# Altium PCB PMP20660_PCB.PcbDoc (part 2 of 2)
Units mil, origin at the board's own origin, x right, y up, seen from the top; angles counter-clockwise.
Board outline 3850 x 3650 mil, 6 copper layers (Top Layer, MidLayer1, MidLayer2, MidLayer3, MidLayer4, Bottom Layer), stack 61.3 mil thick; 110 components, 43 nets, 1166 pads, 406 vias.
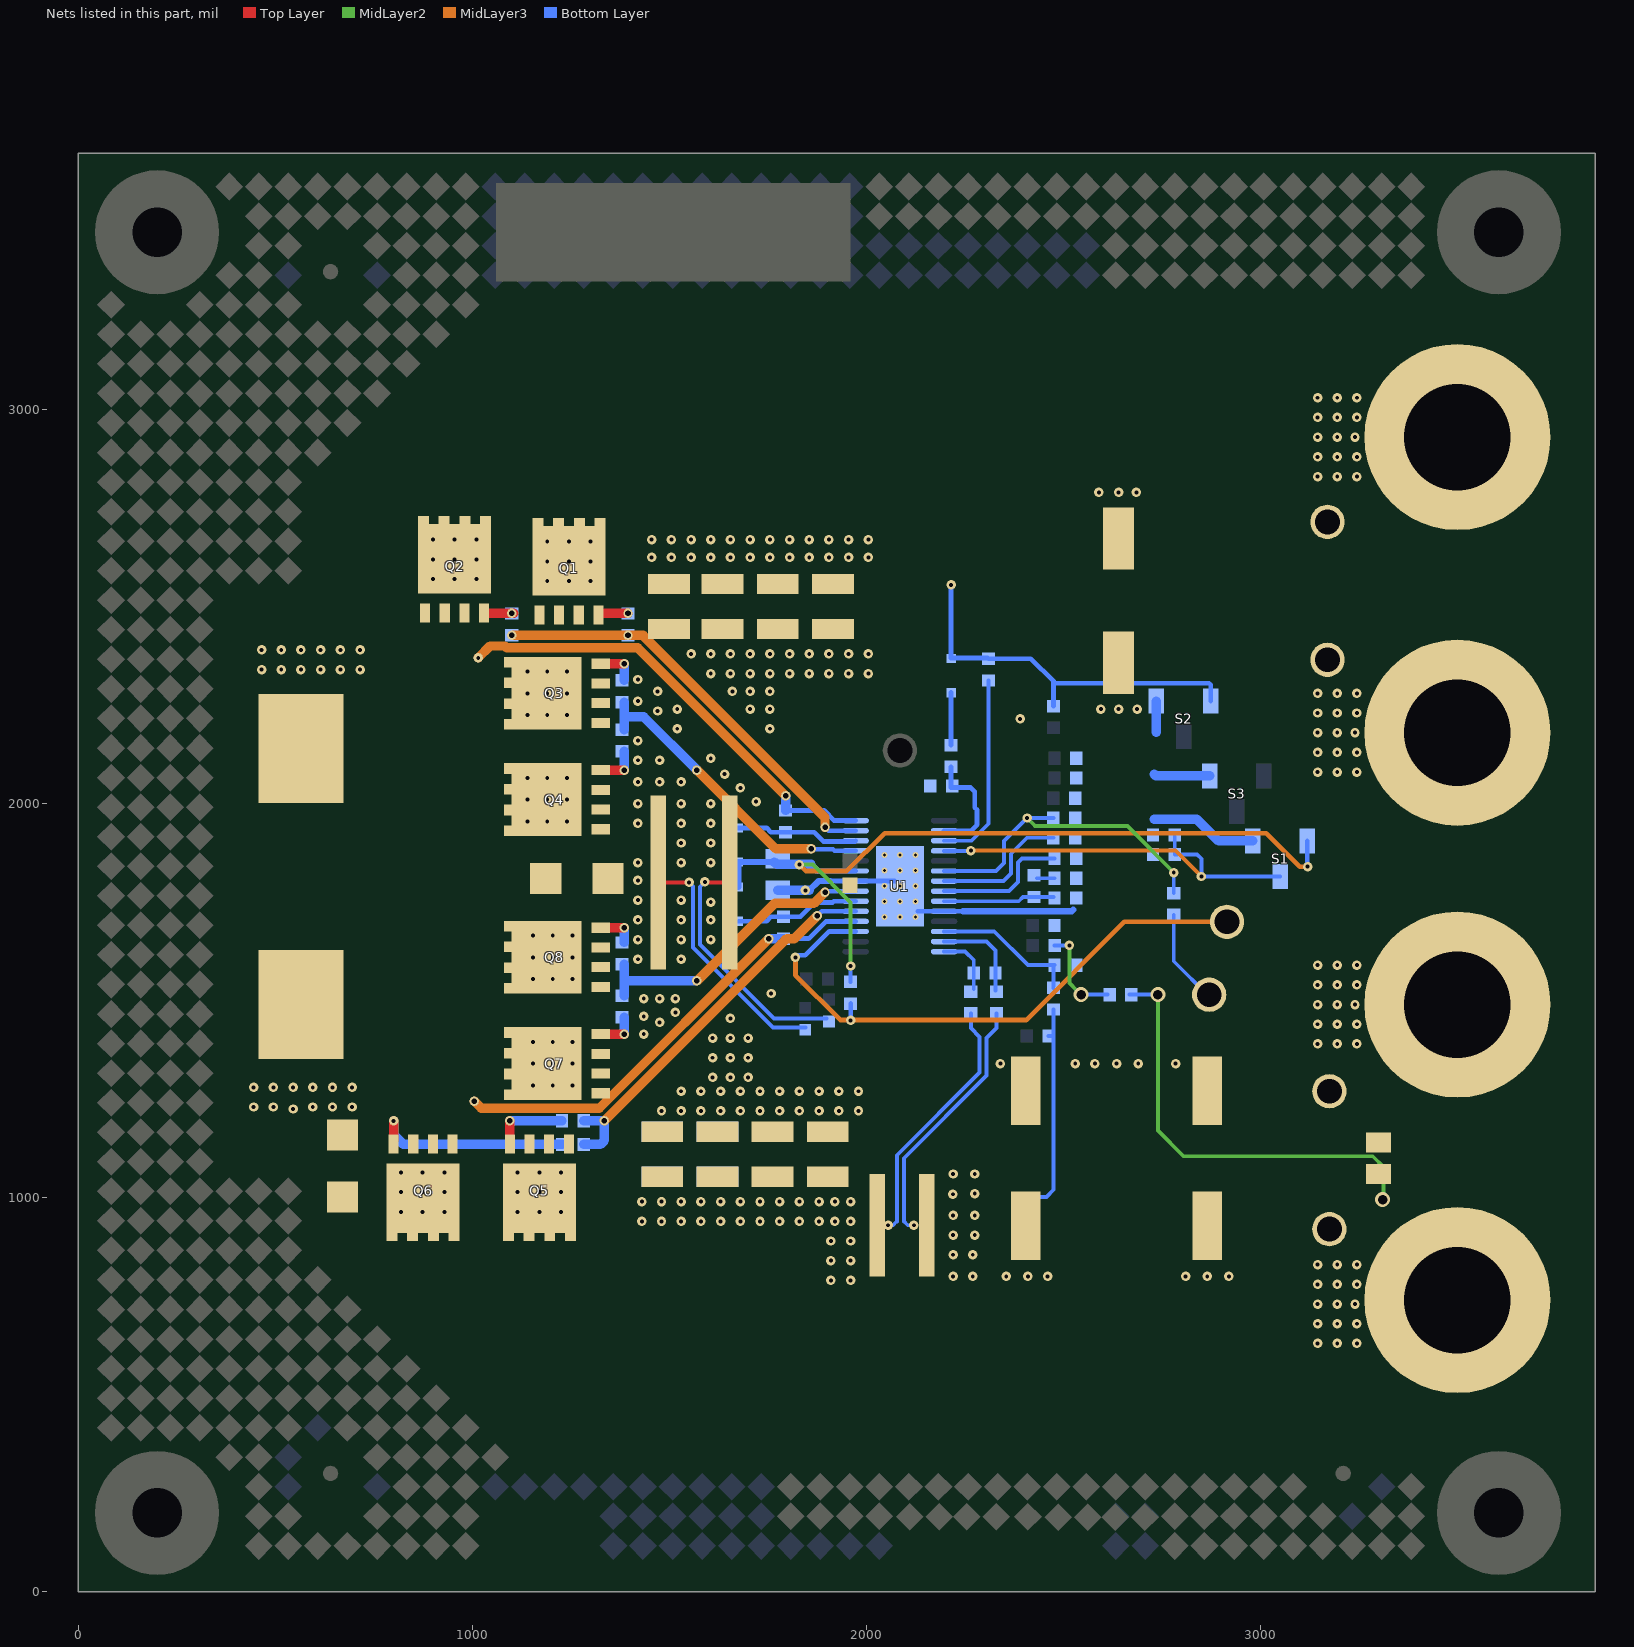
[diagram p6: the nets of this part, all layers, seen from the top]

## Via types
v1: diameter 24, hole 10, Top Layer to Bottom Layer, tented both sides, 272 vias
v2: diameter 24, hole 10, Top Layer to Bottom Layer, 97 vias
v3: diameter 24, hole 14, Top Layer to Bottom Layer, 19 vias
v4: diameter 15.75, hole 7.87, Top Layer to Bottom Layer, 15 vias
v5: diameter 38, hole 24, Top Layer to Bottom Layer, 2 vias
v6: diameter 38, hole 24, Top Layer to Bottom Layer, tented both sides, 1 vias

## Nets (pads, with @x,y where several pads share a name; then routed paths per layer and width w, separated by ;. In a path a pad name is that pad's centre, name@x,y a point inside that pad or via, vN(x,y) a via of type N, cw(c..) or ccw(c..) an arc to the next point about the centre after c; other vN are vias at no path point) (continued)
GND: C1.2 C2.2 C3.2 C4.2 C5.2 C6.2 C7.2 C8.2 C9.2 C10.2 C11.2 C12.2 C13.2 C14.2 C16.1 C17.2 C21.2 C23.2 C25.2 C26.2 C27.2 C28.2 C29.2 C30.2 J2.1 J4.1 R7.1 R8.2 R18.1 R19.1 R20.1 R22.1 R23.1 S1.1 S2.1 S3.1 TP2.1 TP4.1 U1.10 U1.22 U1.29 | length 1824.9
  Top Layer w10: v2@1591.16,1800 R7.1@1653.25,1800
  Bottom Layer w10: v2(1590,1801.16) 1577.87,1789.03 1577.87,1642.13 1765.83,1454.17 1824.63,1454.17 ; R8.2@1899.17,1454.17 1865.37,1454.17 ; 1824.63,1454.17 1824.67,1454.13 ; 1824.67,1454.13 1865.33,1454.13 ; 1865.33,1454.13 1865.37,1454.17
  Bottom Layer w12: 1908.43,1803.43 U1.22@1972.8,1803.43 U1.29@2072.2,1803.43 ; U1.29@2130,1726.65 U1.10@2197.2,1726.65 2245,1726.65
  Bottom Layer w16: v2@1855,1780 1878.43,1803.43 1908.43,1803.43 ; 2245,1726.65 2521.02,1726.65 2525,1730.63
  Bottom Layer w24: C16.1@1775,1780 v2(1845,1780) v2@1855,1780 ; 2730,1960 2838.98,1960 2893.7,1905.28 S1.1@2981.1,1905.28 ; 2730,2075 2734.72,2070.28 S3.1@2871.1,2070.28 ; 2736.1,2181.1 S2.1@2736.1,2260.28
  other v1: 1480,1220 1530,1220 1580,1220 1630,1220 1680,1220 1730,1220 1780,1220 1830,1220 1880,1220 1930,1220 1980,1220 1530,1270 1580,1270 1630,1270 1680,1270 1730,1270 1780,1270 1830,1270 1880,1270 1930,1270 1980,1270 1610,1305 1655,1305 1700,1305 2530,1340 2580,1340 2635,1340 2690,1340 2785,1340 1610,1355 1655,1355 1700,1355 3145,1390 3195,1390 3245,1390 1610,1405 1655,1405 1700,1405 3145,1440 3195,1440 3245,1440 1655,1455 3145,1490 3195,1490 3240,1490 1758.01,1518.03 3145,1540 3195,1540 3245,1540 3145,1590 3195,1590 3245,1590 1605,1655 1605,1705 1605,1750 1605,1850 1605,1900 1605,1950 1605,2000 1720,2005 1680,2040 1640,2075 3145,2080 3195,2080 3245,2080 1605,2115 3145,2130 3195,2130 3245,2130 3145,2180 3195,2180 3240,2180 1755,2190 2390,2215 3145,2230 3195,2230 3245,2230 1705,2240 1755,2240 2595,2240 2640,2240 2686.89,2240 3145,2280 3195,2280 3245,2280 1660,2285 1705,2285 1755,2285 1605,2330 1655,2330 1705,2330 1755,2330 1805,2330 1855,2330 1905,2330 1955,2330 2005,2330 1555,2380 1605,2380 1655,2380 1705,2380 1755,2380 1805,2380 1855,2380 1905,2380 1955,2380 2005,2380
  other v2: 2340,1340
  other v4: 2045.63,1711.89 2085,1711.89 2124.37,1711.89 2045.63,1751.26 2085,1751.26 2124.37,1751.26 2045.63,1790.63 2085,1790.63 2124.37,1790.63 2045.63,1830 2085,1830 2124.37,1830 2045.63,1869.37 2085,1869.37 2124.37,1869.37
HO1: R2.2 R3.2 U1.27 | length 1076.1
  MidLayer3 w24: v3@1105,2427.44 1105,2426.95 v3(1395,2426.95) 1433.13,2426.95 1895,1965.08 v3(1895,1940)
  Bottom Layer w12: 1903.62,1931.38 U1.27@1972.8,1931.38
  other v3: 1100,2427.44
HO2: R24.2 R25.2 U1.19 | length 1017.1
  MidLayer3 w24: v3(1335.08,1195) 1784.32,1644.24 1784.32,1644.32 1797.44,1657.44 1817.44,1657.44 v3(1875,1715)
  Bottom Layer w12: v3(1875,1715) 1886.65,1726.65 U1.19@1972.8,1726.65
  Bottom Layer w24: R25.2@1282.56,1135 1325,1135 1335.08,1145.08 v3(1335.08,1195) R24.2@1282.56,1195
LO1: R4.2 R5.2 U1.25 | length 798.4
  MidLayer3 w24: v3(1570,2085) 1770,1885 v3(1860,1885)
  Bottom Layer w12: v3(1860,1885) 1860.75,1884.25 1915,1884.25 1919.06,1880.2 U1.25@1972.8,1880.2
  Bottom Layer w24: R5.2@1385,2187.56 1385,2220 ; R4.2@1385,2257.44 1385,2220 ; v3(1570,2085) 1435,2220 1385,2220
LO2: R26.2 R27.2 U1.21 | length 758.1
  MidLayer3 w24: v3@1570,1549.86 1767.01,1746.87 1866.87,1746.87 v3(1895,1775)
  Bottom Layer w12: v3@1897.83,1777.83 U1.21@1972.8,1777.83
  Bottom Layer w24: R26.2@1385,1512.56 1385,1550 ; R27.2@1385,1592.44 1385,1550 ; v3(1570,1550) 1385,1550
MODE: C26.1 R19.2 S1.2 U1.4 | length 1046.7
  MidLayer3 w10: v2(2265,1880.63) 2784.37,1880.63 v2(2850,1815)
  Bottom Layer w10: U1.4@2197.2,1880.2 2264.57,1880.2 v2(2265,1880.63) ; R19.2@2782.56,1920.63 C26.1@2782.56,1870.63 2839.37,1870.63 2850,1860 v2(2850,1815) S1.2@3049.72,1815
NetC17_1: C17.1 R9.1 U1.2 | length 290.6
  Bottom Layer w12: U1.2@2197.2,1931.38 2265.75,1931.38 2280.87,1946.5 2280.87,1983.93 2275,1989.8 2275,2030.63 2265,2040.63 C17.1@2215,2040.63 ; C17.1@2215,2043.07 R9.1@2215,2093.07
NetC18_2: C18.2 D4.1 U1.26 | length 312.6
  Bottom Layer w12: D4.1@1675,1938.31 1746.69,1938.31 1757.56,1927.44 C18.2@1795,1927.44 1867.56,1927.44 1890.87,1904.13 1971.13,1904.13 U1.26@1972.8,1905.79
NetC19_1: C19.1 D5.1 U1.20 | length 318.7
  Bottom Layer w12: D5.1@1675,1701.69 1746.69,1701.69 1757.56,1712.56 C19.1@1790,1712.56 1832.56,1712.56 1869.13,1749.13 1914.13,1749.13 1917.24,1752.24 U1.20@1972.8,1752.24
NetC20_1: C20.1 TP7.1 | length 241.6
  Bottom Layer w10: C20.1@2780,1717.44 2780,1600 TP7.1@2867.82,1512.18
NetC20_2: C20.2 R20.2 U1.6 | length 847.9
  MidLayer2 w10: v2(2407.8,1963.43) 2428.46,1942.76 2662.24,1942.76 v2(2780,1825)
  Bottom Layer w10: U1.6@2197.2,1829.02 2329.4,1829.02 2349.25,1848.87 2349.25,1904.88 v2(2407.8,1963.43) R20.2@2474.64,1963.43 ; C20.2@2780,1772.56 v2(2780,1825)
NetC21_1: C21.1 U1.8 | length 343.8
  Bottom Layer w10: U1.8@2197.2,1777.83 2362.2,1777.83 2385,1800.63 2385,1850.63 2395,1860.63 C21.1@2477.44,1860.63
NetC22_1: C22.1 C28.1 U1.9 | length 282.3
  Bottom Layer w10: U1.9@2197.2,1752.24 2386.61,1752.24 2397.44,1763.07 C22.1@2425,1763.07 C28.1@2475,1763.07
NetC22_2: C22.2 R23.2 | length 44.9
  Bottom Layer w10: C22.2@2432.56,1810.63 R23.2@2477.44,1810.63
NetC24_1: C24.1 R16.1 U1.13 | length 242.1
  Bottom Layer w10: U1.13@2197.2,1649.88 2305.12,1649.88 2327.56,1627.44 C24.1@2327.56,1570 R16.1@2327.56,1525
NetC24_2: C24.2 R21.1 U1.14 | length 156.8
  Bottom Layer w10: U1.14@2197.2,1624.29 2250.71,1624.29 2272.44,1602.56 C24.2@2272.44,1570 R21.1@2272.44,1530
NetC29_1: C29.1 U1.7 | length 352.3
  Bottom Layer w10: U1.7@2197.2,1803.43 2347.8,1803.43 2367.13,1822.76 2367.13,1872.76 2407.8,1913.43 C29.1@2474.64,1913.43
NetD2_2: D2.2 Q3.1 Q3.2 Q3.3 Q4.1 Q4.2 Q4.3 Q7.1 Q7.2 Q7.3 Q8.1 Q8.2 Q8.3 R6.2 R7.2 | length 616.2
  Top Layer w10: R7.2@1472.15,1800 v2(1550,1800)
  Bottom Layer w10: v2(1550,1800) 1560,1790 1560,1634.72 1762.72,1432 R6.2@1845,1432
  other v1: 1435,1415 1475,1445 1435,1460 1515,1470 1435,1505 1475,1505 1515,1505 1420,1605 1530,1605 1420,1655 1530,1655 1420,1705 1530,1705 1420,1755 1530,1755 1420,1805 1420,1850 1530,1850 1530,1900 1420,1950 1530,1950 1420,2000 1530,2000 1420,2055 1475,2055 1530,2055 1420,2110 1475,2110 1420,2160 1520,2190 1470,2235 1520,2240 1420,2260 1470,2285 1420,2315
NetD3_1: D3.1 R9.2 | length 133.5
  Bottom Layer w12: R9.2@2215,2148.19 D3.1@2215,2281.69
NetQ1_4: Q1.4 R2.1 | length 70.7
  Top Layer w24: Q1.4@1324.27,2483.05 v3(1395,2483.05)
NetQ2_4: Q2.4 R3.1 | length 68.8
  Top Layer w24: Q2.4@1036.22,2482.56 v3(1100,2482.56) v3@1105,2482.56
NetQ3_4: Q3.4 R4.1 | length 101.2
  Top Layer w24: Q3.4@1326.22,2355 v3(1385,2355)
  Bottom Layer w24: R4.1@1385,2312.56 v3(1385,2355)
NetQ4_4: Q4.4 R5.1 | length 106.2
  Top Layer w24: Q4.4@1326.22,2085 v3(1385.55,2085)
  Bottom Layer w24: v3@1385,2085.55 R5.1@1385,2132.44
NetQ5_4: Q5.4 R24.1 | length 191.2
  Top Layer w24: Q5.4@1095,1136.22 v3(1095,1195)
  Bottom Layer w24: v3(1095,1195) R24.1@1227.44,1195
NetQ6_4: Q6.4 R25.1 | length 521.6
  Top Layer w24: Q6.4@800,1146.22 v2(800,1195)
  Bottom Layer w24: v2(800,1195) 800,1160 825,1135 R25.1@1227.44,1135
NetQ7_4: Q7.4 R26.1 | length 101.2
  Top Layer w24: Q7.4@1326.22,1415 v3(1385,1415)
  Bottom Layer w24: v3(1385,1415) R26.1@1385,1457.44
NetQ8_4: Q8.4 R27.1 | length 96.2
  Top Layer w24: Q8.4@1326.22,1685 v3(1385,1685)
  Bottom Layer w24: R27.1@1385,1647.56 v3(1385,1685)
NetR10_1: R10.1 TP5.1 U1.17 | length 1513.1
  MidLayer3 w12: v2(1820,1610) 1820,1565 1934.36,1450.64 2405.08,1450.64 2654.45,1700 TP5.1@2915,1700 TP5.1@2915.13,1700
  Bottom Layer w12: v2(1820,1610) 1825,1615 1845,1615 1905.47,1675.47 U1.17@1972.8,1675.47 ; v2(1960,1450) R10.1@1960,1492.44
NetR11_2: R11.2 R14.2 | length 228.2
  MidLayer2 w10: v2(2515,1640) 2515,1545 v5@2535,1525
  Bottom Layer w10: R14.2@2477.56,1640 v2(2515,1640) ; v5(2545,1515) R11.2@2612.44,1515
NetR15_1: R15.1 U1.3 | length 494.2
  Bottom Layer w10: U1.3@2197.2,1905.79 2266.85,1905.79 2310,1948.94 R15.1@2310,2312.44
SW1: C18.1 D2.1 L1.1 Q1.1 Q1.2 Q1.3 Q2.1 Q2.2 Q2.3 Q3.5 Q3.6 Q3.7 Q3.8 Q3.9 Q4.5 Q4.6 Q4.7 Q4.8 Q4.9 U1.28 | length 1175.7
  MidLayer3 w24: v2(1015,2370) 1045,2400 1082.36,2400 1086.8,2395.57 1091.3,2395.57 1091.8,2395.07 1419.93,2395.07 v3(1795,2020)
  Bottom Layer w12: C18.1@1795,1982.56 1892.44,1982.56 1918.03,1956.97 U1.28@1972.8,1956.97
  Bottom Layer w24: C18.1@1795,1982.56 v3(1795,2020)
  other v1: 465,2340 515,2340 565,2340 615,2340 665,2340 715,2340 465,2390 515,2390 565,2390 615,2390 665,2390 715,2390
  other v2: 1140,1955 1190,1955 1240,1955 1140,2010 1190,2010 1240,2010 1140,2065 1190,2065 1240,2065 1140,2225 1190,2225 1240,2225 1140,2280 1190,2280 1240,2280 1140,2335 1190,2335 1240,2335
SW2: C19.2 D1.2 L1.2 Q5.1 Q5.2 Q5.3 Q6.1 Q6.2 Q6.3 Q7.5 Q7.6 Q7.7 Q7.8 Q7.9 Q8.5 Q8.6 Q8.7 Q8.8 Q8.9 U1.18 | length 1171.7
  MidLayer3 w24: v3(1005,1245) 1023.13,1226.87 1321.87,1226.87 v3(1752.44,1657.44)
  Bottom Layer w12: C19.2@1790,1657.44 1854.03,1657.44 1897.65,1701.06 U1.18@1972.8,1701.06
  Bottom Layer w24: v3(1752.44,1657.44) C19.2@1790,1657.44
  other v1: 545,1225 445,1230 495,1230 595,1230 645,1230 695,1230 445,1280 495,1280 545,1280 595,1280 645,1280 695,1280
  other v2: 1154,1285 1204,1285 1254,1285 1154,1340 1204,1340 1254,1340 1154,1395 1204,1395 1254,1395 1154,1555 1204,1555 1254,1555 1154,1610 1204,1610 1254,1610 1154,1665 1204,1665 1254,1665
VCC: C16.2 D4.2 D5.2 R10.2 S1.3 U1.23 | length 2177.5
  MidLayer2 w10: v2(1830,1845) 1864.13,1845 1960,1749.13 v2(1960,1587.87) v2@1960,1580
  MidLayer3 w12: v2(1830,1845) 1845.87,1829.13 1950.47,1829.13 2046.35,1925 3015,1925 3100,1840 v2(3120,1840)
  Bottom Layer w10: R10.2@1960,1547.56 v2@1960,1580
  Bottom Layer w12: 1875.98,1829.02 U1.23@1972.8,1829.02 ; v2@3118.9,1841.1 S1.3@3118.9,1905.28
  Bottom Layer w16: D5.2@1675,1788.31 D4.2@1675,1851.69 C16.2@1766.69,1851.69 ; 1859.41,1845.59 1875.98,1829.02
  Bottom Layer w24: C16.2@1766.69,1851.69 1772.79,1845.59 1859.41,1845.59
VIN: C1.1 C2.1 C3.1 C4.1 C5.1 D3.2 J1.1 Q1.5 Q1.6 Q1.7 Q1.8 Q1.9 Q2.5 Q2.6 Q2.7 Q2.8 Q2.9 R13.2 R15.2 S2.3 TP1.1 | length 973.3
  Bottom Layer w12: v1(2215,2555) 2215,2369.47 R15.2@2308.09,2369.47 ; R15.2@2310,2367.56 2417.44,2367.56 2475,2310 ; R13.2@2475,2247.56 2475,2250 2475,2310 ; S2.3@2873.9,2260.28 2873.9,2301.1 2869.35,2305.65 2479.35,2305.65 2475,2310
  other v1: 1455,2625 1505,2625 1555,2625 1605,2625 1655,2625 1705,2625 1755,2625 1805,2625 1855,2625 1905,2625 1955,2625 2005,2625 1455,2670 1505,2670 1555,2670 1605,2670 1655,2670 1705,2670 1755,2670 1805,2670 1855,2670 1905,2670 1955,2670 2005,2670 2590,2790 2640,2790 2685,2790 3145,2830 3195,2830 3245,2830 3145,2880 3195,2880 3245,2880 3145,2930 3195,2930 3240,2930 3145,2980 3195,2980 3245,2980 3145,3030 3195,3030 3245,3030
  other v2: 1190,2565 1245,2565 1300,2565 900,2570 955,2570 1010,2570 1190,2615 1245,2615 1300,2615 900,2620 955,2620 1010,2620 1190,2665 1245,2665 1300,2665 900,2670 955,2670 1010,2670
VOSNS: C30.1 R17.2 U1.12 | length 370.6
  Bottom Layer w10: U1.12@2197.2,1675.47 2324.53,1675.47 2410,1590 C30.1@2477.44,1590 ; R17.2@2475,1532.56 C30.1@2475,1587.56
VOSNS+: C6.1 C7.1 C8.1 C9.1 C10.1 C11.1 D1.1 Q5.5 Q5.6 Q5.7 Q5.8 Q5.9 Q6.5 Q6.6 Q6.7 Q6.8 Q6.9 R1.1 R21.2 | length 649.9
  Bottom Layer w10: v2(2055,930) 2067.13,930 2077.13,940 2077.13,1107.4 2287.13,1317.4 2287.13,1407.87 2265,1430 R21.2@2265,1467.44
  other v1: 1910,790 1960,790 1910,840 1960,840 1910,890 1960,890 1430,940 1480,940 1530,940 1580,940 1630,940 1680,940 1730,940 1780,940 1830,940 1880,940 1920,940 1960,940 1430,990 1480,990 1530,990 1580,990 1630,990 1680,990 1730,990 1780,990 1830,990 1880,990 1920,990 1960,990
  other v2: 819,964 874,964 929,964 1115,964 1170,964 1225,964 819,1014 874,1014 929,1014 1115,1014 1170,1014 1225,1014 819,1064 874,1064 929,1064 1115,1064 1170,1064 1225,1064
VOSNS-: C12.1 C13.1 C14.1 J3.1 R1.2 R11.1 R12.1 R16.2 R17.1 TP3.1 | length 2304.7
  MidLayer2 w10: v5(2740,1515) 2740,1170 2805,1105 3285,1105 3312.5,1077.5 v6@3312.5,997.5
  Bottom Layer w10: v2(2120.51,930) 2105,930 2095,940 2095,1100 2305,1310 2305,1405 2330,1430 R16.2@2330,1467.44 ; 2410,1001.57 2456.57,1001.57 2475,1020 R12.1@2475,1410 ; R12.1@2462.56,1410 R12.1@2475,1410 ; R17.1@2475,1477.44 R12.1@2475,1410 ; R11.1@2668.05,1515 R11.1@2672.56,1515 v5(2740,1515)
  other v1: 3145,630 3195,630 3245,630 3145,680 3195,680 3245,680 3145,730 3195,730 3240,730 3145,780 3195,780 3245,780 2220,800 2270,800 2355,800 2410,800 2460,800 2810,800 2865,800 2920,800 3145,830 3195,830 3245,830 2220,855 2270,855 2220,905 2275,905 2220,955 2275,955 2219.64,1008.59 2275,1010 2220,1060 2275,1060
  other v6: 3310,995
pads on no net: FID1.1 FID2.1 FID3.1 H1.1 H2.1 H3.1 H4.1 Logo1.0 S3.3

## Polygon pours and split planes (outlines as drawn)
GND on MidLayer3 "Top Layer-No Net 6" (solid, remove dead copper, pour order 41): 15,15 15,3625 3825,3625 3825,15
GND on MidLayer4 "Top Layer-No Net 6" (solid, remove dead copper, pour order 42): 20,20 20,3630 3830,3630 3830,20
GND on MidLayer1 "Top Layer-No Net 6" (solid, remove dead copper, pour order 33): 20,20 20,3630 3830,3630 3830,20
VOSNS+ on MidLayer2 "Top Layer-No Net" (solid, remove dead copper, pour order 37): 2065,1090 2065,390 1095,390 595,890 595,1090
VOSNS- on MidLayer2 "Top Layer-No Net 1" (solid, remove dead copper, pour order 38): 3800,390 2115,390 2115,1090 3800,1090
VIN on MidLayer2 "Top Layer-No Net 2" (solid, remove dead copper, pour order 39): 3800,2525 636.1,2525 636.1,2841.1 1070,3275 3800,3275
NetD2_2 on MidLayer2 "Top Overlay-No Net" (solid, remove dead copper, pour order 34): 1302.7,1221.89 1304.59,1220 1395,1220 1565,1390 1565,1775 1499.71,1775 1499.71,1825 1565,1825 1565,2240 1405,2400 1302.7,2400
SW1 on MidLayer2 "Top Layer-No Net 4" (solid, remove dead copper, pour order 36): 1280,1765 1280,2510 395,2510 392.24,2233.86 392.24,1990 915,1990 1140,1765
SW2 on MidLayer2 "Top Layer-No Net 3" (solid, remove dead copper, pour order 35): 1285.08,1110 395,1110 395,1640 920,1640 1015,1735 1279.88,1735
GND on MidLayer2 "M4 3D STEP Bottom-No Net" (solid, remove dead copper, pour order 40): 1415.67,2500 3800.67,2500 3800.67,1875 3350.67,1875 3350.67,1775 3800.67,1775 3800.67,1105 1395.67,1105 1395.67,1195 1575.64,1374.97 1575.64,1524.4 1577.24,1800 1575.71,2065.59 1575.67,2065.63 1575.67,2245 1415.67,2405
SW2 on Bottom Layer "Top Layer-No Net 3" (solid, remove dead copper, pour order 45): 1285,1110 394.92,1110 394.92,1640 919.92,1640 1014.92,1735 1279.79,1735
SW1 on Bottom Layer "Top Layer-No Net 4" (solid, remove dead copper, pour order 46): 1280,1765 1280,2510 395,2510 392.24,2233.86 392.24,1990 915,1990 1140,1765
VIN on Bottom Layer "Top Layer-No Net 2" (solid, remove dead copper, pour order 49): 3802.39,2524.36 638.49,2524.36 638.49,2840.47 1072.39,3274.36 3802.39,3274.36
VOSNS- on Bottom Layer "Top Layer-No Net 1" (solid, remove dead copper, pour order 48): 3800,390 2115,390 2115,1090 3800,1090
VOSNS+ on Bottom Layer "Top Layer-No Net" (solid, remove dead copper, pour order 47): 2065,1090 2065,390 1095,390 595,890 595,1090
GND on Bottom Layer "Top Layer-No Net 5" (solid, remove dead copper, pour order 43): 2745,2190 2745,1560.63 2454.33,1552.24 2457.76,1739.96 2515,1739.96 2515,2190
NetD2_2 on Bottom Layer "Top Overlay-No Net" (solid, remove dead copper, pour order 44): 1305,1221.89 1306.89,1220 1397.3,1220 1567.3,1390 1567.3,2240 1407.3,2400 1305,2400
GND on Bottom Layer "Bottom Layer-No Net 1" (solid, remove dead copper, pour order 50): 3800,2505 3800,1880 3350,1880 3350,1784.36 3799.36,1784.36 3800,1785 3800,1110 1395,1110 1395,1200 1574.97,1379.97 1577.24,1382.24 1577.24,1765.64 1577.24,1767.24 1585,1775 1625.69,1775 1625.69,1824 1582.08,1824 1578.55,1827.54 1577.24,1828.85 1577.24,2240 1577.24,2247.76 1415,2410 1419.81,2414.81 1419.81,2505
VIN on Top Layer "Top Layer-No Net 2" (solid, remove dead copper, pour order 31): 3800,2525 636.1,2525 636.1,2841.1 1070,3275 3800,3275
VOSNS- on Top Layer "Top Layer-No Net 1" (solid, remove dead copper, pour order 30): 3800,390 2115,390 2115,1090 3800,1090
GND on Top Layer "M4 3D STEP Bottom-No Net" (solid, remove dead copper, pour order 32): 1415,2505 3800,2505 3800,1880 3350,1880 3350,1780 3800,1780 3800,1110 1395,1110 1395,1200 1574.97,1379.97 1574.97,1529.4 1575.04,2070.59 1575,2070.63 1575,2250 1415,2410
VOSNS+ on Top Layer "Top Layer-No Net" (solid, remove dead copper, pour order 29): 2065,1090 2065,390 1095,390 595,890 595,1090
SW1 on Top Layer "Top Layer-No Net 4" (solid, remove dead copper, pour order 28): 1280,1765 1280,2510 395,2510 392.24,2233.86 392.24,1990 915,1990 1140,1765
SW2 on Top Layer "Top Layer-No Net 3" (solid, remove dead copper, pour order 27): 1285.08,1110 395,1110 395,1640 920,1640 1015,1735 1279.88,1735
NetD2_2 on Top Layer "Top Overlay-No Net" (solid, remove dead copper, pour order 26): 1302.7,1221.89 1304.59,1220 1395,1220 1565,1390 1565,2240 1405,2400 1302.7,2400

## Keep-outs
Keep-Out Layer:
  lines w7: -3.5,0 ccw(c0,0) 0,-3.5 ; -3.5,0 ccw(c0,0) 0,-3.5 ; -3.5,0 -3.5,3650 ; -3.5,3650 cw(c0,3650) 0,3653.5 ; -3.5,3650 cw(c0,3650) 0,3653.5 ; 0,-3.5 3850,-3.5 ; 0,3653.5 3850,3653.5 ; 3850,-3.5 ccw(c3850,0) 3853.5,0 ; 3850,-3.5 ccw(c3850,0) 3853.5,0 ; 3850,3653.5 cw(c3850,3650) 3853.5,3650 ; 3850,3653.5 cw(c3850,3650) 3853.5,3650 ; 3853.5,0 3853.5,3650
  text ".Layer_Name" at 577,-858.49 h60

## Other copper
Top Layer:
  pour cut-out: 1635,1775 1585,1775 1580,1770 1575,1765.64 1562.77,1765.64 1555,1775 1495,1775 1495,1825 1496,1824 1555,1825 1562.76,1831.07 1575.01,1831.08 1582.08,1824 1635,1824
  pour cut-out: 3824.76,1784.36 3350,1784.36 3350,1880 3350.63,1880.63 3824.76,1880.63
  pour cut-out: 2101.81,799.09 2078.19,799.09 2078.19,1061.89 2101.81,1061.89
  text ".CopyrightYear" at 2132,3350 h60
  text "TI" at 2408,3350 h60
  text "©" at 2015,3346.48 h105
  text ".Layer_Name" at 577,-858.49 h60
MidLayer1:
  pour cut-out: 3824.76,1784.36 3350,1784.36 3350,1880 3350.63,1880.63 3824.76,1880.63
  pour cut-out: 1574.36,1825.53 1602.13,1825.53 1610,1817.66 1610,1783.3 1602.34,1775.53 1574.36,1775.53
  text ".layer_Name" at 575,-860 h60
MidLayer2:
  pour cut-out: 1574.36,1825.53 1602.13,1825.53 1610,1817.66 1610,1783.3 1602.34,1775.53 1574.36,1775.53
  pour cut-out: 2105,950 2135,950 2145,940 2145,920 2135,910 2105,910
  pour cut-out: 2075,910 2045,910 2035,920 2035,940 2045,950 2075,950
  pour cut-out: 3824.76,1784.36 3350,1784.36 3350,1880 3350.63,1880.63 3824.76,1880.63
  text ".layer_Name" at 575,-860 h60
MidLayer3:
  pour cut-out: 1574.36,1824.47 1602.13,1824.47 1610,1816.6 1610,1782.24 1602.34,1774.47 1574.36,1774.47
  pour cut-out: 3824.76,1784.36 3350,1784.36 3350,1880 3350.63,1880.63 3824.76,1880.63
  text ".layer_Name" at 575,-860 h60
MidLayer4:
  pour cut-out: 1565,1780 1535,1780 1525,1790 1525,1810 1535,1820 1565,1820
  pour cut-out: 3827.06,1788.11 3352.31,1789.37 3352.31,1879.37 3352.94,1880 3827.06,1880
  pour cut-out: 1574.36,1824.47 1602.13,1824.47 1610,1816.6 1610,1782.24 1602.34,1774.47 1574.36,1774.47
  text ".layer_Name" at 575,-860 h60
Bottom Layer:
  pour cut-out: 1550,1800 1550,1620 1565,1605 1565,1800
  pour cut-out: 1881.38,1470 1928.62,1470 1928.62,1411.38 1923,1417 1883.01,1417
  pour cut-out: 3827.06,1783.73 3352.31,1783.73 3352.31,1879.37 3352.94,1880 3827.06,1880
  pour cut-out: 1574.36,1824.52 1602.13,1824.52 1610,1816.65 1610,1782.29 1602.34,1774.52 1574.36,1774.52
  pour cut-out: 2100,950 2130,950 2140,940 2140,920 2130,910 2100,910
  pour cut-out: 2075,910 2045,910 2035,920 2035,940 2045,950 2075,950
  pour cut-out: 1565,1780 1535,1780 1525,1790 1525,1810 1535,1820 1565,1820
  pour cut-out: 2955,1865 3010,1865 3010,1945 2955,1945
  pour cut-out: 2705,2225 2765,2225 2765,2295 2705,2295
  pour cut-out: 2845,2030 2900,2030 2900,2110 2845,2110
  text "MADE IN U.S." at 1250,86.5 h60
  text "UL94V-0" at 2529.5,86.5 h60
  text ".Layer_Name" at 577,-858.49 h60

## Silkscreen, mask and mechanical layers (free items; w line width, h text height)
Top Overlay:
  region: 2750,150 2450,150 2450,50 2750,50
  text "VIN" at 2945,3200 h70
  text "6-36VDC" at 2665,3100 h70
  text "+" at 3132,2894 h120
  text "-" at 3138,2095 h120
  text "-" at 3140,1456 h120
  text "+" at 3130.29,699.04 h120
  text "VOUT" at 3000,530 h70
  text "12VDC @ 10A" at 2530,410 h70
  text ".PRJ_Number" at 1790,70 h60
  text ".PCB_Rev" at 2270,70 h60
  text "-" at 2390,70 h60
  text ".Layer_Name" at 577,-858.49 h60
Bottom Overlay:
  lines w7: 1790,1505 1790,1520 1815,1545 ; 3035,1755 2990,1755 2970,1775 ; 1815,1545 1800,1545 1815,1530 1815,1545 ; 2970,1775 2985,1775 2970,1760 2970,1775
  text "EN" at 2925,2305 h40
  text "OFF" at 2670,2295 h40 r90
  text "ON" at 2995,2290 h40 r90
  text "DITH" at 3120,2125 h40
  text "OFF" at 2805,2075 h40 r90
  text "MODE" at 3310,1955 h40
  text "CCM" at 3240,1925 h40 r90
  text "DCM" at 3165,1720 h40
  text ".Layer_Name" at 577,-858.49 h60
Top Paste:
  text ".Layer_Name" at 577,-858.49 h60
Bottom Paste:
  text ".Layer_Name" at 577,-858.49 h60
Top Solder:
  text ".Layer_Name" at 577,-858.49 h60
  text ".Layer_Name" at 577,-858.49 h60
Bottom Solder:
  text ".Layer_Name" at 577,-858.49 h60
Drill Guide:
  text ".Layer_Name" at 577,-858.49 h60
M1 Board Outline:
  the board outline again, w8
  text ".Layer_Name" at 577,-858.49 h60
M2 Board Dimensions:
  rectangle: 125,-410.5 500,-285.5
  rectangle: 0,-285.5 125,-160.5
  lines w7: 0,-285.5 1000,-285.5 ; 125,-410.5 125,-160.5 ; 250,-410.5 250,-160.5 ; 500,-410.5 500,-160.5 ; 750,-410.5 750,-160.5 ; 0,-410.5 0,-160.5 1000,-160.5 1000,-410.5 0,-410.5
  text ".Layer_Name" at 577,-858.49 h60
M3 3D STEP Top:
  text ".Layer_Name" at 577,-858.49 h60
M4 3D STEP Bottom:
  text ".Layer_Name" at 577,-858.49 h60
M5 Assembly Top:
  lines w10: -292,-930.17 6308,-930.17 ; -292,-726.83 6310,-726.83 ; -292,-523.5 -292,-1133.5 3713,-1133.5 6310,-1133.5 6310,-523.5 -291.5,-523.5 -291.5,-1133.5 1284,-1133.5 ; 2173,-1133.5 2173,-523.5 ; 3440,-726.83 3440,-523.5 ; 4280,-726.83 4280,-523.5 ; 4902,-1140 4902,-937.17
  text "COMPONENTS MARKED 'DNP' SHOULD NOT BE POPULATED." at 1153.5,-318.5 h60
  text "ASSEMBLY VARIANT:" at 1153,-434 h60
  text ".VariantName" at 2189,-434 h60
  text "PCB VIEWED FROM TOP SIDE" at -228.5,-655.67 h60
  text "BOARD #:" at 2248,-655.67 h60
  text ".PRJ_Number" at 2793.5,-655.67 h60
  text "REV:" at 3638,-655.67 h60
  text ".PCB_Rev" at 3929.5,-655.67 h60
  text "SVN REV:" at 4476,-655.67 h60
  text ".VersionControl_RevNumber" at 4982,-655.67 h60
  text "IGNORE ->" at -228.5,-858.49 h60
  text "PLOT NAME =" at -228.5,-1064.34 h60
  text ".plot_File_Name" at 577,-1064.34 h60
  text "GENERATED    :" at 2250,-1064.34 h60
  text ".Print_Date" at 3119.5,-1064.34 h60
  text ".Print_Time" at 3848.5,-1064.34 h60
  text "TEXAS INSTRUMENTS" at 5113,-1064.34 h60
M6 Assembly Bottom:
  lines w10: -292.5,-727.33 6309.5,-727.33 ; -290.5,-930.67 6309.5,-930.67 ; 1115.5,-1140.5 1115.5,-937.67 ; 1737.5,-727.33 1737.5,-524 ; 2577.5,-727.33 2577.5,-524 ; 3844.5,-1134 3844.5,-524 ; 4733.5,-1134 6309,-1134 6309,-524 -292.5,-524 -292.5,-1134 2304.5,-1134 6309.5,-1134 6309.5,-524
  text "COMPONENTS MARKED 'DNP' SHOULD NOT BE POPULATED." at 6102,-318 h60
  text ".VariantName" at 5058,-434 h60
  text "ASSEMBLY VARIANT:" at 6097,-434 h60
  text ".VersionControl_RevNumber" at 1035.5,-656.17 h60
  text "SVN REV:" at 1541.5,-656.17 h60
  text ".PCB_Rev" at 2088,-656.17 h60
  text "REV:" at 2379.5,-656.17 h60
  text ".PRJ_Number" at 3224,-656.17 h60
  text "BOARD #:" at 3769.5,-656.17 h60
  text "PCB VIEWED FROM BOTTOM SIDE" at 6246,-656.17 h60
  text "IGNORE ->" at 2547.85,-858.49 h60
  text "TEXAS INSTRUMENTS" at 904.5,-1064.84 h60
  text ".Print_Time" at 2169,-1064.84 h60
  text ".Print_Date" at 2898,-1064.84 h60
  text "GENERATED    :" at 3767.5,-1064.84 h60
  text ".plot_File_Name" at 5440.5,-1064.84 h60
  text "PLOT NAME =" at 6246,-1064.84 h60
M9 Title Sheet:
  drawing of 57 lines, arcs and shapes, not listed
  text "1" at 739.84,8036.5 h70
  text "2" at 3235.5,8036.5 h70
  text "3" at 5724.84,8036.5 h70
  text "4" at 8231.51,8036.5 h70
  text "5" at 10730.5,8036.5 h70
  text "6" at 13235.5,8036.5 h70
  text "A" at -416.5,6893.5 h70
  text "A" at 14383.5,6893.5 h70
  text "B" at -416.5,4513.5 h70
  text "B" at 14383.5,4513.5 h70
  text "C" at -416.5,2138.5 h70
  text "C" at 14383.5,2138.5 h70
  text "PROJECT TITLE:" at 11343.5,277.5 h45
  text ".PRJ_Title" at 11393.5,144.17 h70
  text "DESIGNED FOR:" at 11343.5,-23.5 h45
  text ".PRJ_Customer" at 11393.5,-163.5 h70
  text "D" at -416.5,-231.5 h70
  text "D" at 14383.5,-231.5 h70
  text "FILE NAME:" at 11343.5,-323.5 h45
  text ".PCB_File_Name_No_Path" at 11393.5,-443.5 h70
  text "Texas Instruments (TI) and/or its licensors do not warrant the accuracy or completeness of this specification" at 6374,-605.34 h45
  text "ENGINEER:" at 11343.5,-613.5 h45
  text "LAYOUT BY:" at 12848.5,-613.5 h45
  text "or any information contained therein. TI and/or its licensors do not warrant that this design will meet" at 6329.01,-718 h45
  text ".PRJ_Engineer" at 11393.5,-768.49 h70
  text ".PCB_Layout" at 12899,-768.49 h70
  text "the specifications, will be suitable for your application or fit for any particular purpose, or will operate in" at 6329.01,-830.67 h45
  text ".Layer_Name" at 577,-858.49 h60
  text "ALTIUM DESIGNER VERSION:" at 12848.5,-923.5 h45
  text "an implementation. TI and/or its licensors do not warrant that the design is production worthy. You should" at 6329.01,-943.33 h45
  text "completely validate and test your design implementation to confirm the system functionality for your application." at 6374,-1056 h45
  text ".print_Scale" at 11393.5,-1056.83 h70
  text ".Application_BuildNumber" at 12899,-1056.83 h70
  text "1" at 739.84,-1263.5 h70
  text "2" at 3235.5,-1263.5 h70
  text "3" at 5724.84,-1263.5 h70
  text "4" at 8231.51,-1263.5 h70
  text "5" at 10730.5,-1263.5 h70
  text "6" at 13235.5,-1263.5 h70
M10 Fab Notes:
  drawing of 185 lines, arcs and shapes, not listed
  text "DESIGN INFORMATION" at 12381.02,5910 h60
  text "MIN. TRACK WIDTH:" at 11736.46,5730 h60
  text "8" at 12832.7,5730 h60
  text "MIL" at 12987.46,5730 h60
  text "MIN. CLEARANCE:" at 11736.46,5598 h60
  text "0.2" at 12772.7,5598 h60
  text "mm" at 12987.46,5598 h60
  text "MIN. VIA PAD SIZE:" at 11736.46,5466 h60
  text "24" at 12802.71,5466 h60
  text "MIL" at 12987.46,5466 h60
  text "0.05mm (2MIL)" at 12431.46,5324.29 h60
  text "MINIMUM ANNULAR RING" at 11407.23,5320 h60
  text "EXTERNAL" at 13139.46,5320 h60
  text "PER" at 11607.23,5202 h60
  text "IPC-D-275 CLASS 2 LEVEL C" at 11827.23,5202 h60
  text "MIL, HOLES" at 13315.46,5089.71 h60
  text "+/-" at 12923,5089 h60
  text "+/-" at 13777,5089 h60
  text "REGISTRATION TOLERANCES:" at 11407.23,5084 h60
  text "METAL" at 12607,5084 h60
  text "5" at 13183.2,5084 h60
  text "3" at 14016.2,5084 h60
  text "MIL" at 14132.46,5084 h60
  text "MATERIAL:" at 11332.46,4874.54 h60
  text "FR-4 High Tg" at 12318.9,4734.21 h60
  text "FR-408" at 11753.46,4725.64 h60
  text "X" at 12165.46,4725.64 h60
  text "OTHER" at 13241.46,4725.64 h60
  text "62 MIL (1.6mm) +/-10%" at 12073.56,4562.92 h60
  text "THICKNESS:" at 11407.23,4558.64 h60
  text "X" at 11945.4,4558.64 h60
  text "OTHER" at 13358.46,4558.64 h60
  text "TOLERANCE:" at 11407.23,4400.64 h60
  text "X" at 12246.53,4400.64 h60
  text "ANSI IPC-6012 TYPE 3 CLASS 2" at 12433.48,4400.64 h60
  text "OTHER +/-" at 12433.46,4244.64 h60
  text "BOW & TWIST:" at 11407.23,4087.64 h60
  text "X" at 12246.53,4087.64 h60
  text "ANSI IPC-6012 TYPE 3 CLASS 2" at 12433.48,4087.64 h60
  text "OTHER +/-" at 12433.46,3929.13 h60
  text "DRILLING:" at 11332.46,3790.64 h60
  text "REFERENCE:" at 11407.23,3673.64 h60
  text "X" at 12055.46,3673.64 h60
  text "AS SHOWN" at 12242.46,3673.64 h60
  text "X" at 12956.46,3673.64 h60
  text "NC_DRILL FILES" at 13093.46,3673.64 h60
  text "PTH MIN COPPER THICKNESS:" at 11407.23,3515.64 h60
  text "X" at 12757.46,3515.64 h60
  text "1MIL" at 12894.46,3515.64 h60
  text "OTHER" at 13391.46,3515.64 h60
  text "BOARD FINISH:" at 11332.46,3356.64 h60
  text "SILKSCREEN:" at 11487.68,3238.64 h60
  text "X" at 12436.46,3238.64 h60
  text "TOP" at 12562.46,3238.64 h60
  text "X" at 12946.46,3238.64 h60
  text "BOTTOM" at 13073.46,3238.64 h60
  text "SILKSCREEN COLOR:" at 11487.68,3071.64 h60
  text "X" at 12435.42,3071.64 h60
  text "WHITE" at 12562.46,3071.64 h60
  text "OTHER" at 13073.46,3071.64 h60
  text "SOLDER RESIST COLOR:" at 11487.68,2901.64 h60
  text "X" at 12055.42,2742.44 h60
  text "GREEN" at 12182.46,2742.44 h60
  text "BLUE" at 12773.46,2742.44 h60
  text "OTHER" at 13311.46,2742.44 h60
  text "IMMERSION GOLD (ENIG)" at 12393.46,2553.92 h60
  text "ENEPIG" at 13731,2550.64 h60
  text "SURFACE FINISH:" at 11332.46,2549.64 h60
  text "X" at 12206.51,2549.64 h60
  text "IMM. TIN/SILVER OR EQUIV" at 11662,2392.64 h60
  text "OTHER" at 13093.46,2392.64 h60
  text "ARRAY/PANEL:" at 11332.46,2213.64 h60
  text "CUT AND TRIM PER MECH LAYER 1" at 12393.46,2209.35 h60
  text "X" at 13070,2060 h60
  text "N.C. ROUTE" at 12393.46,2057.64 h60
  text "V. SCORE" at 13259.46,2057.64 h60
  text "CERTIFICATION:" at 11332.46,1920.64 h60
  text "MATERIALS AND WORKMANSHIP FOR ALL PCBS" at 12057.46,1920.64 h60
  text "TO MEET OR EXCEED THE REQUIREMENTS OF:" at 12057.46,1822.64 h60
  text "X" at 11683.96,1686.13 h60
  text "ANSI IPC-A-600F CLASS ->" at 11822.96,1686.13 h60
  text "X" at 13462.02,1686.13 h60
  text "2" at 13580.96,1686.14 h60
  text "1" at 13265.96,1684.64 h60
  text "3" at 13934.96,1684.64 h60
  text "X" at 11686.02,1526.64 h60
  text "UL 94V-0" at 11822.96,1526.64 h60
  text "X" at 12498.02,1526.64 h60
  text "RoHS" at 12634.96,1526.64 h60
  text "OTHER" at 13279.36,1526.64 h60
  text "PER ORDER" at 13676.42,1526.64 h60
  text "ADDITIONAL REQUIREMENTS:" at 11332.46,1385.64 h60
  text "MICROSECTION:" at 11407.23,1270.64 h60
  text "YES" at 12312.96,1270.64 h60
  text "REQUIRED" at 13174.46,1114.49 h60
  text "BARE BOARD ELEC. TEST:" at 11407.23,1111.64 h60
  text "NONE" at 12712.96,1111.64 h60
  text "X" at 13047.46,1111.64 h60
  text "PER ORDER" at 13766.46,1111.64 h60
  text "MANUFACTURER'S UL:" at 11407.23,954.64 h60
  text "RAIL" at 12572.96,950.35 h60
  text "METAL" at 13064.77,950.35 h60
  text "X" at 13440,950 h60
  text "SILK" at 13576.46,950.35 h60
  text ".Layer_Name" at 577,-858.49 h60
M11 Gerber Information:
  lines w10: -292,-930.17 6308,-930.17 ; -292,-726.83 6310,-726.83 ; -292,-523.5 -292,-1133.5 3713,-1133.5 6310,-1133.5 6310,-523.5 -291.5,-523.5 -291.5,-1133.5 1284,-1133.5 ; 2173,-1133.5 2173,-523.5 ; 3440,-726.83 3440,-523.5 ; 4280,-726.83 4280,-523.5 ; 4902,-1140 4902,-937.17
  text "ALL ARTWORK VIEWED FROM TOP SIDE" at -228.5,-655.67 h60
  text "BOARD #:" at 2248,-655.67 h60
  text ".PRJ_Number" at 2793.5,-655.67 h60
  text "REV:" at 3638,-655.67 h60
  text ".PCB_Rev" at 3929.5,-655.67 h60
  text "SVN REV:" at 4476,-655.67 h60
  text ".VersionControl_RevNumber" at 4982,-655.67 h60
  text "LAYER NAME =" at -228.5,-858.49 h60
  text "PLOT NAME =" at -228.5,-1064.34 h60
  text ".plot_File_Name" at 577,-1064.34 h60
  text "GENERATED    :" at 2250,-1064.34 h60
  text ".Print_Date" at 3119.5,-1064.34 h60
  text ".Print_Time" at 3848.5,-1064.34 h60
  text "TEXAS INSTRUMENTS" at 5113,-1064.34 h60
M12 Stackup:
  drawing of 399 lines, arcs and shapes, not listed
  text "Layer" at 9821.2,7870 h60
  text "Name" at 10231.11,7870 h60
  text "Material" at 11160.85,7870 h60
  text "Thickness" at 12020.62,7870 h60
  text "Constant" at 12670.46,7870 h60
  text "Board Layer Stack" at 13240.32,7870 h60
  text "1" at 9821.2,7750 h60
  text "Top Overlay" at 10231.11,7750 h60
  text "2" at 9821.2,7630 h60
  text "Top Solder" at 10231.11,7630 h60
  text "Solder Resist" at 11160.85,7630 h60
  text "0.40mil" at 12020.62,7630 h60
  text "3.5" at 12670.46,7630 h60
  text "3" at 9821.2,7510 h60
  text "Top Layer" at 10231.11,7510 h60
  text "Copper" at 11160.85,7510 h60
  text "2.80mil" at 12020.62,7510 h60
  text "4" at 9821.2,7390 h60
  text "Dielectric1" at 10231.11,7390 h60
  text "FR-4" at 11160.85,7390 h60
  text "8.90mil" at 12020.62,7390 h60
  text "4.2" at 12670.46,7390 h60
  text "5" at 9821.2,7270 h60
  text "MidLayer1" at 10231.11,7270 h60
  text "Copper" at 11160.85,7270 h60
  text "2.80mil" at 12020.62,7270 h60
  text "6" at 9821.2,7150 h60
  text "Dielectric2" at 10231.11,7150 h60
  text "FR-4" at 11160.85,7150 h60
  text "8.90mil" at 12020.62,7150 h60
  text "4.8" at 12670.46,7150 h60
  text "7" at 9821.2,7030 h60
  text "MidLayer2" at 10231.11,7030 h60
  text "Copper" at 11160.85,7030 h60
  text "2.80mil" at 12020.62,7030 h60
  text "8" at 9821.2,6910 h60
  text "Dielectric3" at 10231.11,6910 h60
  text "FR-4" at 11160.85,6910 h60
  text "8.90mil" at 12020.62,6910 h60
  text "4.2" at 12670.46,6910 h60
  text "9" at 9821.2,6790 h60
  text "MidLayer3" at 10231.11,6790 h60
  text "Copper" at 11160.85,6790 h60
  text "2.80mil" at 12020.62,6790 h60
  text "10" at 9821.2,6670 h60
  text "Dielectric4" at 10231.11,6670 h60
  text "FR-4" at 11160.85,6670 h60
  text "8.90mil" at 12020.62,6670 h60
  text "4.8" at 12670.46,6670 h60
  text "11" at 9821.2,6550 h60
  text "MidLayer4" at 10231.11,6550 h60
  text "Copper" at 11160.85,6550 h60
  text "2.80mil" at 12020.62,6550 h60
  text "12" at 9821.2,6430 h60
  text "Dielectric5" at 10231.11,6430 h60
  text "FR-4" at 11160.85,6430 h60
  text "8.90mil" at 12020.62,6430 h60
  text "4.8" at 12670.46,6430 h60
  text "13" at 9821.2,6310 h60
  text "Bottom Layer" at 10231.11,6310 h60
  text "Copper" at 11160.85,6310 h60
  text "2.80mil" at 12020.62,6310 h60
  text "14" at 9821.2,6190 h60
  text "Bottom Solder" at 10231.11,6190 h60
  text "Solder Resist" at 11160.85,6190 h60
  text "0.40mil" at 12020.62,6190 h60
  text "3.5" at 12670.46,6190 h60
  text "15" at 9821.2,6070 h60
  text "Bottom Overlay" at 10231.11,6070 h60
  text ".Layer_Name" at 577,-858.49 h60
M13 Component Bodies Top:
  text ".Layer_Name" at 577,-858.49 h60
M14 Component Bodies Bottom:
  text ".Layer_Name" at 577,-858.49 h60
M15 Courtyards Top:
  text ".Layer_Name" at 577,-858.49 h60
M16 Courtyards Bottom:
  text ".Layer_Name" at 577,-858.49 h60
Drill Drawing:
  text ".legend" at 5122.5,725.5 h60
  text "Drill Table" at 5147.5,540.5 h60
  text ".Layer_Name" at 577,-858.49 h60

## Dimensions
0,-410.5 to 1000,-410.5 on M2 Board Dimensions
0,0 to 3850,0 on M2 Board Dimensions
0,0 to 0,3650 on M2 Board Dimensions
